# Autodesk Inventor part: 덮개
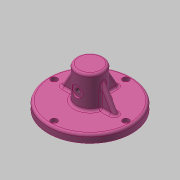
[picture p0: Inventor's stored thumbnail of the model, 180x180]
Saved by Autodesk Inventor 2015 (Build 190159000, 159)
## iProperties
Created: 2017-08
Part Number: 덮개
Material: 알루미늄 6061
Document SubType Name: Modeling
Designer: mduedu
Density: 2.71 g/cm^3
Mass: 331.485 g
Surface Area: 305.526 cm^2
Volume: 122.319 cm^3
Appearance: 분홍색
Author: mduedu
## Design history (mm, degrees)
sketch "스케치1"
  geometry: C1 r 52.5 at (0, 0); 1 further point
  constraints: 1 centre point, 1 coincident
  dimensions: "d55" = 105 diameter of C1
extrude "돌출1" new body sketch "스케치1" distance "d5" = 10; taper "d6" = 0 deg
sketch "스케치2"
  geometry: C1 r 17 at (0, 0); 1 further point
  constraints: 1 centre point, 1 coincident
  dimensions: "d74" = 34 diameter of C1
extrude "돌출2" join sketch "스케치2" distance "d9" = 40; taper "d10" = 0 deg
sketch "스케치3"
  geometry: C1 r 37 at (0, 0); 1 further point
  constraints: 1 centre point, 1 coincident
  dimensions: "d56" = 74 diameter of C1
extrude "돌출3" join sketch "스케치3" distance "d12" = 8; taper "d13" = 0 deg
sketch "스케치4"
  geometry: C1 r 33 at (0, 0); 1 further point
  constraints: 1 centre point, 1 coincident
  dimensions: "d57" = 66 diameter of C1
extrude "돌출4" cut sketch "스케치4" distance "d16" = 7; taper "d17" = 0 deg
sketch "스케치5"
  geometry: C1 r 9 at (0, 0); 1 further point
  constraints: 1 centre point, 1 coincident
  dimensions: "d18" = 18 diameter of C1
extrude "돌출5" cut sketch "스케치5" distance "d19" = 47; taper "d20" = 0 deg
node "작업 평면1"
sketch "스케치11"
  geometry: L1 (-52.5, -10)-(52.5, -10) reference; 2 further points
  constraints: 1 vertical alignment
  dimensions: "d78" = 28 distance from line of point (0, 18) L1
hole "구멍5" sketch "스케치11" at (0, 18) diameter "d79" = 5.917; stored, may be unused: countersink angle "d83" = 90 deg, drill point angle "d85" = 118 deg; dims "d80" = 6, "d81" = 14, "d82" = 2, "d84" = 8
fillet "모깎기9" dims "d86" = 3
fillet "모깎기5" dims "d40" = 1
sketch "스케치12"
  geometry: C1 r 2.5 at (0, 0); 1 further point
  constraints: 1 centre point, 1 coincident
  dimensions: "d87" = 5 diameter of C1
extrude "돌출6" join sketch "스케치12" distance "d88" = 3; taper "d89" = 0 deg
fillet "모깎기10" dims "d91" = 1
chamfer "모따기1" distance "d41" = 1; stored, may be unused: second distance "d42" = 2, angle "d43" = 45 deg
fillet "모깎기7" dims "d45" = 3
fillet "모깎기8" dims "d46" = 3
sketch "스케치10" dims "d59" = 90
  geometry: 3 further points
  constraints: 2 vertical alignment, 1 coincident, 2 other
hole "구멍4" sketch "스케치10" at (0, 45) diameter "d60" = 4.5; stored, may be unused: countersink angle "d64" = 90 deg, drill point angle "d66" = 118 deg; dims "d61" = 6, "d62" = 8, "d63" = 4.6, "d65" = 8
sketch "스케치13"
  geometry: L1 (52.5, 7)-(52.5, 0) reference; L2 (52.5, 0)-(47.25, 0) reference; L3 (47.25, 0)-(47.25, 5.4) reference; L4 (47.25, 5.4)-(49, 5.4) reference; L5 (49, 5.4)-(49, 10) reference; L6 (49, 10)-(49.5, 10) reference; L7 (-49.5, 10)-(-49, 10) reference; L8 (-49, 10)-(-49, 5.4) reference; L9 (-49, 5.4)-(-47.25, 5.4) reference; L10 (-47.25, 5.4)-(-47.25, 0) reference; L11 (-47.25, 0)-(-52.5, 0) reference; L12 (-52.5, 0)-(-52.5, 7) reference; L13 (-3.5, 46)-(-8, 46) reference; L14 (-9, 45)-(-9, -1) reference; L15 (-9, -1)-(-30, -1) reference; L16 (-33, -4)-(-33, -8) reference; L17 (-33, -8)-(-36, -8) reference; L18 (-36, -8)-(-37, -7) reference; L19 (-37, -7)-(-37, 0) reference; L20 (-37, 0)-(-42.75, 0) reference; L21 (-42.75, 0)-(-42.75, 5.4) reference; L22 (-42.75, 5.4)-(-41, 5.4) reference; L23 (-41, 5.4)-(-41, 10) reference; L24 (-41, 10)-(-20, 10) reference; L25 (-17, 13)-(-17, 47) reference; L26 (-14, 50)-(14, 50) reference; L27 (17, 47)-(17, 13) reference; L28 (20, 10)-(41, 10) reference; L29 (41, 10)-(41, 5.4) reference; L30 (41, 5.4)-(42.75, 5.4) reference; L31 (42.75, 5.4)-(42.75, 0) reference; L32 (42.75, 0)-(37, 0) reference; L33 (37, 0)-(37, -7) reference; L34 (37, -7)-(36, -8) reference; L35 (36, -8)-(33, -8) reference; L36 (33, -8)-(33, -4) reference; L37 (30, -1)-(9, -1) reference; L38 (9, -1)-(9, 45) reference; L39 (8, 46)-(3.5, 46) reference; L40 (2.5, 45)-(2.5, 43) reference; L41 (2.5, 43)-(-2.5, 43) reference; L42 (-2.5, 43)-(-2.5, 45) reference; L43 (17, 40)-(34.321, 10); L44 (-49.5, 10)-(49.5, 10) reference; A1 r 3 centre (49.5, 7) between (52.5, 7) and (49.5, 10) reference; A2 r 3 centre (-49.5, 7) between (-49.5, 10) and (-52.5, 7) reference; A3 r 1 centre (-3.5, 45) between (-2.5, 45) and (-3.5, 46) reference; A4 r 1 centre (-8, 45) between (-8, 46) and (-9, 45) reference; A5 r 3 centre (-30, -4) between (-30, -1) and (-33, -4) reference; A6 r 3 centre (-20, 13) between (-20, 10) and (-17, 13) reference; A7 r 3 centre (-14, 47) between (-14, 50) and (-17, 47) reference; A8 r 3 centre (14, 47) between (17, 47) and (14, 50) reference; A9 r 3 centre (20, 13) between (17, 13) and (20, 10) reference; A10 r 3 centre (30, -4) between (33, -4) and (30, -1) reference; A11 r 1 centre (8, 45) between (9, 45) and (8, 46) reference; A12 r 1 centre (3.5, 45) between (3.5, 46) and (2.5, 45) reference; 1 further point
  constraints: 2 end point, 2 point on line
  dimensions: "d98" = 120 deg angle of L43 L28; "d99" = 30 distance from line of L43.start L44
feature "리브1" sketch "스케치13" dims "d100" = 1, "d101" = 6, "d102" = 0, "d103" = 0, "d104" = 1, "d105" = 1
fillet "모깎기11" dims "d106" = 3
fillet "모깎기12" dims "d107" = 3
node "솔리드1"
pattern_circular "원형 패턴1" dims angle "d68" = 360 deg
pattern_circular "원형 패턴2" dims "d109" = 270 deg
node "절단 모서리 투영1"
